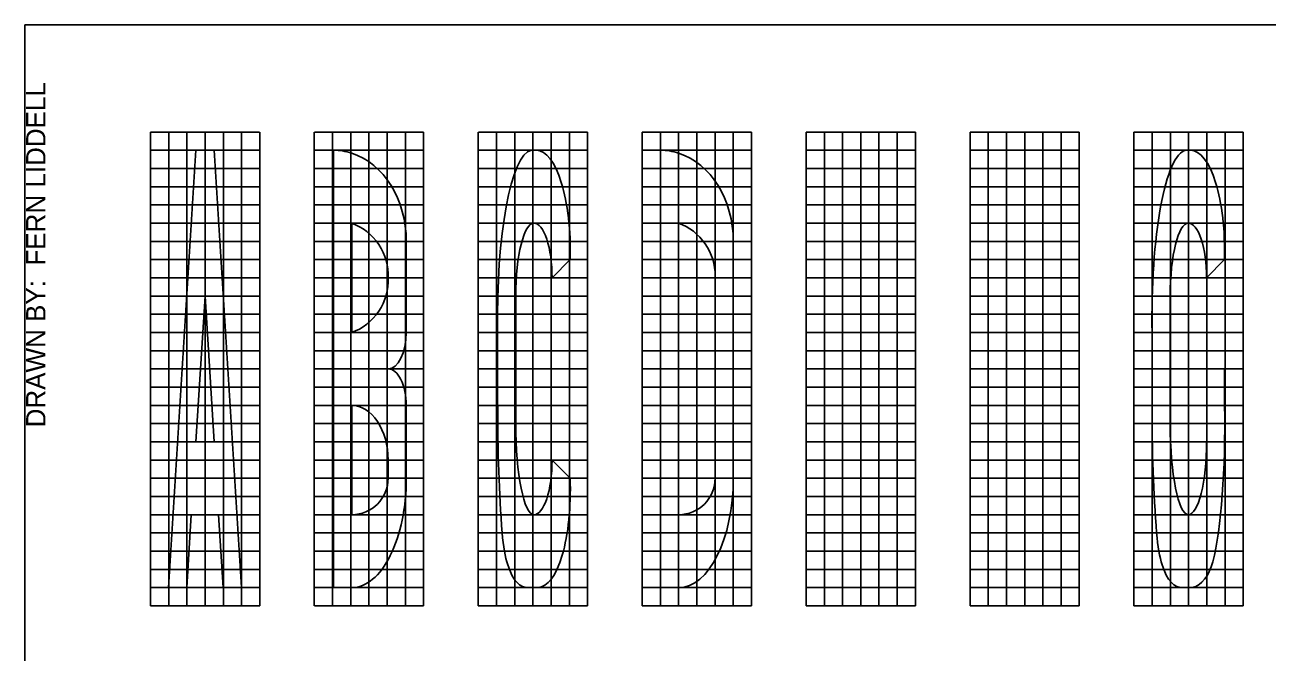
# Model space of a CAD drawing. Extents: x 99862 to 103151, y 100000 to 102076.
# Drawn here: x 99862 to 100885, y 101559 to 102076 of the extents above; entities that cross this region are included whole.
import ezdxf

# ---------------------------------------------------------------- set-up
doc = ezdxf.new("R2010")
doc.units = 0
for name, color, linetype in [('Level 1', 7, 'Continuous'), ('Level 20', 7, 'Continuous'), ('Level 4', 7, 'Continuous'), ('Level 62', 7, 'Continuous')]:
    doc.layers.add(name, color=color, linetype=linetype)

msp = doc.modelspace()

# ---------------------------------------------------------------- linework, layer by layer
at = {"layer": 'Level 1'}
msp.add_lwpolyline([(99862, 99999.5), (103151, 99999.5), (103151, 102075.5), (99862, 102075.5)], close=True, dxfattribs=at)
at = {"layer": 'Level 20'}
for p, q in [((100116.2, 101972.3), (100116.2, 101612.3)), ((100283.2, 101972.3), (100279.2, 101972.3)), ((100385.5, 101972.3), (100385.5, 101868.7)), ((100822.1, 101972.3), (100818.2, 101972.3)), ((100131.2, 101822.3), (100131.2, 101912.3)), ((100400.5, 101868.7), (100400.5, 101912.3)), ((100176.2, 101822.3), (100176.2, 101897.3)), ((100445.5, 101868.7), (100445.5, 101897.3)), ((100296.2, 101867.3), (100311.2, 101882.3)), ((100835.2, 101867.3), (100850.1, 101882.3)), ((100385.5, 101868.7), (100385.5, 101867.3)), ((100385.5, 101867.3), (100385.5, 101717.3)), ((100400.5, 101867.3), (100400.5, 101868.7)), ((100400.5, 101717.3), (100400.5, 101867.3)), ((100430.5, 101868.7), (100430.5, 101867.3)), ((100430.5, 101867.3), (100430.5, 101717.3)), ((100445.5, 101867.3), (100445.5, 101868.7)), ((100445.5, 101717.3), (100445.5, 101867.3)), ((100266.4, 101747.3), (100266.4, 101852.3)), ((100805.3, 101747.3), (100805.3, 101852.3)), ((100251.4, 101822.3), (100251.4, 101762.3)), ((100790.4, 101822.3), (100790.4, 101762.3)), ((100850.2, 101792.3), (100820.3, 101792.3)), ((100820.3, 101792.3), (100820.3, 101732.3)), ((100850.2, 101762.3), (100850.2, 101792.3)), ((100131.2, 101672.3), (100131.2, 101762.3)), ((100176.2, 101702.3), (100176.2, 101762.3)), ((100820.3, 101732.3), (100835.2, 101732.3)), ((100161.2, 101717.3), (100161.2, 101702.3)), ((100311.2, 101702.3), (100296.2, 101717.3)), ((100385.5, 101717.3), (100385.5, 101715.4)), ((100400.5, 101715.4), (100400.5, 101717.3)), ((100430.5, 101717.3), (100430.5, 101715.4)), ((100445.5, 101715.4), (100445.5, 101717.3)), ((100385.5, 101715.4), (100385.5, 101612.3)), ((100400.5, 101672.3), (100400.5, 101715.4)), ((100430.5, 101715.4), (100430.5, 101702.3)), ((100445.5, 101702.3), (100445.5, 101715.4)), ((100116.2, 101612.3), (100128.4, 101612.3)), ((100128.4, 101612.3), (100131.2, 101612.3)), ((100277.3, 101612.3), (100284.7, 101612.3)), ((100385.5, 101612.3), (100400.5, 101612.3)), ((100816.2, 101612.3), (100820.3, 101612.3)), ((100820.3, 101612.3), (100823.6, 101612.3))]:
    msp.add_line(p, q, dxfattribs=at)
for points in [[(99999.1, 101672.3), (100021.6, 101672.3), (100025.4, 101612.3), (100040.4, 101612.3), (100017.9, 101972.3), (100002.9, 101972.3), (99980.4, 101612.3), (99995.4, 101612.3)], [(100535.5, 101762.3), (100580.5, 101762.3), (100580.5, 101822.3), (100535.5, 101822.3), (100535.5, 101912.3), (100580.5, 101912.3), (100580.5, 101972.3), (100535.5, 101972.3), (100528, 101972.3), (100520.5, 101972.3), (100520.5, 101612.3), (100531.7, 101612.3), (100535.5, 101612.3), (100580.5, 101612.3), (100580.5, 101672.3), (100535.5, 101672.3)], [(100670.5, 101912.3), (100715.5, 101912.3), (100715.5, 101972.3), (100670.5, 101972.3), (100663, 101972.3), (100655.5, 101972.3), (100655.5, 101612.3), (100670.5, 101612.3), (100670.5, 101762.3), (100700.5, 101762.3), (100700.5, 101822.3), (100670.5, 101822.3)], [(100017.9, 101732.3), (100002.9, 101732.3), (100010.4, 101852.3)]]:
    msp.add_lwpolyline(points, close=True, dxfattribs=at)
for centre in [(100131.2, 101702.3), (100400.5, 101702.3)]:
    msp.add_arc(centre, 30, 270, 0, dxfattribs=at)
for centre, major_axis, ratio, start_param, end_param in [((100116.2, 101897.3), (0, -75), 0.8, 2.888912, 3.141593), ((100116.2, 101897.3), (0, -75), 0.8, 1.570796, 2.888912), ((100281.8, 101828.3), (1.4, -144.1), 0.211336, 3.181491, 4.752287), ((100281.3, 101882.8), (-2, -89.5), 0.334281, 1.57277, 3.143567), ((100385.5, 101897.3), (0, -75), 0.8, 2.888912, 3.141593), ((100385.5, 101897.3), (0, -75), 0.8, 1.570796, 2.888912), ((100820.8, 101828.3), (1.4, -144.1), 0.211348, 3.18149, 4.752287), ((100820.2, 101882.8), (-2, -89.5), 0.3343, 1.572771, 3.143568), ((100128.5, 101878), (21.2, -31.8), 0.784465, 0.785398, 2.356194), ((100281.3, 101852.3), (0, -60), 0.248912, 3.141593, 4.712389), ((100281.3, 101867.3), (0, -45), 0.331883, 1.570796, 3.141593), ((100397.8, 101878), (21.2, -31.8), 0.784465, 0.826187, 2.356194), ((100820.3, 101852.3), (0, -60), 0.248926, 3.141593, 4.712389), ((100820.3, 101867.3), (0, -45), 0.331902, 1.570796, 3.141593), ((100128.5, 101856.5), (-21.2, -31.8), 0.784465, 0.785398, 2.356194), ((100161.2, 101822.3), (0, -30), 0.5, 0, 1.570796), ((100161.2, 101762.3), (0, -30), 0.5, 1.570796, 3.141593), ((100131.2, 101717.3), (0, -45), 0.666667, 1.570796, 3.141593), ((100330.2, 101833.5), (-17.5, -354.3), 0.216739, 4.925571, 5.243712), ((100869.2, 101833.5), (-17.5, -354.3), 0.216751, 4.925572, 5.243713), ((100825.9, 101760), (2.2, -149), 0.16287, 0.554923, 1.58392), ((100281.3, 101747.3), (0, -75), 0.19913, 4.712389, 6.283185), ((100820.3, 101747.3), (0, -75), 0.199141, 4.712389, 6.283185), ((100820.3, 101732.3), (0, -60), 0.249371, 6.283185, 7.853982), ((100281.3, 101717.3), (0, -45), 0.331883, 6.283185, 7.853982), ((100131.2, 101702.3), (0, -90), 0.5, 6.283185, 7.853982), ((100281.6, 101701.5), (3.1, -89.2), 0.331181, 6.280966, 7.851763), ((100400.5, 101702.3), (0, -90), 0.5, 0, 1.570796), ((100272.7, 101702.4), (-5.6, -80.6), 0.216756, 5.320454, 5.812319), ((100811.7, 101702.4), (-5.6, -80.6), 0.216768, 5.320456, 5.812321), ((100312.6, 101794.8), (-38.4, -182.3), 0.244216, 5.877043, 6.350091), ((100851.5, 101794.8), (-38.4, -182.3), 0.244228, 5.877049, 6.350097), ((100586.8, 102189.6), (238.9, -576.6), 0.169025, 6.262693, 6.489624)]:
    msp.add_ellipse(centre, major_axis=major_axis, ratio=ratio, start_param=start_param, end_param=end_param, dxfattribs=at)
at = {"layer": 'Level 4'}
for p, q in [((99965.5, 101987.3), (99965.5, 101597.3)), ((99965.5, 101987.3), (100055.4, 101987.3)), ((99980.5, 101987.2), (99980.5, 101597.3)), ((99995.5, 101987.3), (99995.5, 101597.3)), ((100010.5, 101987.3), (100010.5, 101597.3)), ((100025.5, 101987.3), (100025.5, 101597.3)), ((100040.5, 101987.3), (100040.5, 101597.3)), ((100055.5, 101987.3), (100055.5, 101597.3)), ((100100.4, 101987.3), (100100.4, 101597.3)), ((100100.5, 101987.3), (100190.4, 101987.3)), ((100115.4, 101987.3), (100115.4, 101597.3)), ((100130.4, 101987.3), (100130.4, 101597.3)), ((100145.4, 101987.3), (100145.4, 101597.3)), ((100160.4, 101987.3), (100160.4, 101597.3)), ((100175.4, 101987.3), (100175.4, 101597.3)), ((100190.4, 101987.3), (100190.4, 101597.3)), ((100235.5, 101987.3), (100235.5, 101597.3)), ((100235.6, 101987.3), (100325.5, 101987.3)), ((100250.5, 101987.3), (100250.5, 101597.3)), ((100265.5, 101987.3), (100265.5, 101597.3)), ((100280.5, 101987.3), (100280.5, 101597.3)), ((100295.5, 101987.3), (100295.5, 101597.3)), ((100310.5, 101987.3), (100310.5, 101597.3)), ((100325.5, 101987.3), (100325.5, 101597.3)), ((100370.5, 101987.3), (100460.5, 101987.3)), ((100370.5, 101987.3), (100370.5, 101597.3)), ((100385.5, 101987.3), (100385.5, 101597.3)), ((100400.5, 101987.3), (100400.5, 101597.3)), ((100415.5, 101987.3), (100415.5, 101597.3)), ((100430.5, 101987.3), (100430.5, 101597.3)), ((100445.5, 101987.3), (100445.5, 101597.3)), ((100460.5, 101987.3), (100460.5, 101597.3)), ((100505.5, 101987.3), (100595.5, 101987.3)), ((100505.5, 101987.3), (100505.5, 101597.3)), ((100520.5, 101987.3), (100520.5, 101597.3)), ((100535.5, 101987.3), (100535.5, 101597.3)), ((100550.5, 101987.3), (100550.5, 101597.3)), ((100565.5, 101987.3), (100565.5, 101597.3)), ((100580.5, 101987.3), (100580.5, 101597.3)), ((100595.5, 101987.3), (100595.5, 101597.3)), ((100640.5, 101987.3), (100730.5, 101987.3)), ((100640.5, 101987.3), (100640.5, 101597.3)), ((100655.5, 101987.3), (100655.5, 101597.3)), ((100670.5, 101987.3), (100670.5, 101597.3)), ((100685.5, 101987.3), (100685.5, 101597.3)), ((100700.5, 101987.3), (100700.5, 101597.3)), ((100715.5, 101987.3), (100715.5, 101597.3)), ((100730.5, 101987.3), (100730.5, 101597.3)), ((100775.5, 101987.3), (100865.5, 101987.3)), ((100775.5, 101987.3), (100775.5, 101597.3)), ((100790.5, 101987.3), (100790.5, 101597.3)), ((100805.5, 101987.3), (100805.5, 101597.3)), ((100820.5, 101987.3), (100820.5, 101597.3)), ((100835.5, 101987.3), (100835.5, 101597.3)), ((100850.5, 101987.3), (100850.5, 101597.3)), ((100865.5, 101987.3), (100865.5, 101597.3)), ((99965.4, 101972.3), (100055.5, 101972.3)), ((100100.4, 101972.3), (100190.4, 101972.3)), ((100235.4, 101972.3), (100325.5, 101972.3)), ((100370.4, 101972.3), (100460.5, 101972.3)), ((100505.4, 101972.3), (100595.5, 101972.3)), ((100640.4, 101972.3), (100730.5, 101972.3)), ((100775.4, 101972.3), (100865.5, 101972.3)), ((99965.4, 101957.3), (100055.5, 101957.3)), ((100100.4, 101957.3), (100190.4, 101957.3)), ((100235.4, 101957.3), (100325.5, 101957.3)), ((100370.4, 101957.3), (100460.5, 101957.3)), ((100505.4, 101957.3), (100595.5, 101957.3)), ((100640.4, 101957.3), (100730.5, 101957.3)), ((100775.4, 101957.3), (100865.5, 101957.3)), ((99965.6, 101942.3), (100055.5, 101942.3)), ((100100.6, 101942.3), (100190.4, 101942.3)), ((100235.6, 101942.3), (100325.5, 101942.3)), ((100370.6, 101942.3), (100460.5, 101942.3)), ((100505.6, 101942.3), (100595.5, 101942.3)), ((100640.6, 101942.3), (100730.5, 101942.3)), ((100775.6, 101942.3), (100865.5, 101942.3)), ((99965.4, 101927.3), (100055.5, 101927.3)), ((100100.4, 101927.3), (100190.4, 101927.3)), ((100235.4, 101927.3), (100325.5, 101927.3)), ((100370.4, 101927.3), (100460.5, 101927.3)), ((100505.4, 101927.3), (100595.5, 101927.3)), ((100640.4, 101927.3), (100730.5, 101927.3)), ((100775.4, 101927.3), (100865.5, 101927.3)), ((99965.4, 101912.3), (100055.5, 101912.3)), ((100100.4, 101912.3), (100190.4, 101912.3)), ((100235.4, 101912.3), (100325.5, 101912.3)), ((100370.4, 101912.3), (100460.5, 101912.3)), ((100505.4, 101912.3), (100595.5, 101912.3)), ((100640.4, 101912.3), (100730.5, 101912.3)), ((100775.4, 101912.3), (100865.5, 101912.3)), ((99965.5, 101897.3), (100055.5, 101897.3)), ((100100.5, 101897.3), (100190.4, 101897.3)), ((100235.5, 101897.3), (100325.5, 101897.3)), ((100370.5, 101897.3), (100460.5, 101897.3)), ((100505.5, 101897.3), (100595.5, 101897.3)), ((100640.5, 101897.3), (100730.5, 101897.3)), ((100775.5, 101897.3), (100865.5, 101897.3)), ((99965.5, 101882.3), (100055.5, 101882.3)), ((100100.5, 101882.3), (100190.4, 101882.3)), ((100235.5, 101882.3), (100325.5, 101882.3)), ((100370.5, 101882.3), (100460.5, 101882.3)), ((100505.5, 101882.3), (100595.5, 101882.3)), ((100640.5, 101882.3), (100730.5, 101882.3)), ((100775.5, 101882.3), (100865.5, 101882.3)), ((99965.6, 101867.3), (100055.5, 101867.3)), ((100100.6, 101867.3), (100190.4, 101867.3)), ((100235.6, 101867.3), (100325.5, 101867.3)), ((100370.6, 101867.3), (100460.5, 101867.3)), ((100505.6, 101867.3), (100595.5, 101867.3)), ((100640.6, 101867.3), (100730.5, 101867.3)), ((100775.6, 101867.3), (100865.5, 101867.3)), ((99965.6, 101852.3), (100055.5, 101852.3)), ((100100.6, 101852.3), (100190.4, 101852.3)), ((100235.6, 101852.3), (100325.5, 101852.3)), ((100370.6, 101852.3), (100460.5, 101852.3)), ((100505.6, 101852.3), (100595.5, 101852.3)), ((100640.6, 101852.3), (100730.5, 101852.3)), ((100775.6, 101852.3), (100865.5, 101852.3)), ((99965.4, 101837.3), (100055.5, 101837.3)), ((100100.4, 101837.3), (100190.4, 101837.3)), ((100235.4, 101837.3), (100325.5, 101837.3)), ((100370.4, 101837.3), (100460.5, 101837.3)), ((100505.4, 101837.3), (100595.5, 101837.3)), ((100640.4, 101837.3), (100730.5, 101837.3)), ((100775.4, 101837.3), (100865.5, 101837.3)), ((99965.5, 101822.3), (100055.5, 101822.3)), ((100100.5, 101822.3), (100190.4, 101822.3)), ((100235.5, 101822.3), (100325.5, 101822.3)), ((100370.5, 101822.3), (100460.5, 101822.3)), ((100505.5, 101822.3), (100595.5, 101822.3)), ((100640.5, 101822.3), (100730.5, 101822.3)), ((100775.5, 101822.3), (100865.5, 101822.3)), ((99965.4, 101807.3), (100055.5, 101807.3)), ((100100.4, 101807.3), (100190.4, 101807.3)), ((100235.4, 101807.3), (100325.5, 101807.3)), ((100370.4, 101807.3), (100460.5, 101807.3)), ((100505.4, 101807.3), (100595.5, 101807.3)), ((100640.4, 101807.3), (100730.5, 101807.3)), ((100775.4, 101807.3), (100865.5, 101807.3)), ((99965.5, 101792.3), (100055.5, 101792.3)), ((100100.5, 101792.3), (100190.4, 101792.3)), ((100235.5, 101792.3), (100325.5, 101792.3)), ((100370.5, 101792.3), (100460.5, 101792.3)), ((100505.5, 101792.3), (100595.5, 101792.3)), ((100640.5, 101792.3), (100730.5, 101792.3)), ((100775.5, 101792.3), (100865.5, 101792.3)), ((99965.5, 101777.3), (100055.5, 101777.3)), ((100100.5, 101777.3), (100190.4, 101777.3)), ((100235.5, 101777.3), (100325.5, 101777.3)), ((100370.5, 101777.3), (100460.5, 101777.3)), ((100505.5, 101777.3), (100595.5, 101777.3)), ((100640.5, 101777.3), (100730.5, 101777.3)), ((100775.5, 101777.3), (100865.5, 101777.3)), ((99965.4, 101762.3), (100055.5, 101762.3)), ((100100.4, 101762.3), (100190.4, 101762.3)), ((100235.4, 101762.3), (100325.5, 101762.3)), ((100370.4, 101762.3), (100460.5, 101762.3)), ((100505.4, 101762.3), (100595.5, 101762.3)), ((100640.4, 101762.3), (100730.5, 101762.3)), ((100775.4, 101762.3), (100865.5, 101762.3)), ((99965.5, 101747.3), (100055.5, 101747.3)), ((100100.5, 101747.3), (100190.4, 101747.3)), ((100235.5, 101747.3), (100325.5, 101747.3)), ((100370.5, 101747.3), (100460.5, 101747.3)), ((100505.5, 101747.3), (100595.5, 101747.3)), ((100640.5, 101747.3), (100730.5, 101747.3)), ((100775.5, 101747.3), (100865.5, 101747.3)), ((99965.5, 101732.3), (100055.5, 101732.3)), ((100100.5, 101732.3), (100190.4, 101732.3)), ((100235.5, 101732.3), (100325.5, 101732.3)), ((100370.5, 101732.3), (100460.5, 101732.3)), ((100505.5, 101732.3), (100595.5, 101732.3)), ((100640.5, 101732.3), (100730.5, 101732.3)), ((100775.5, 101732.3), (100865.5, 101732.3)), ((99965.5, 101717.3), (100055.5, 101717.3)), ((100100.5, 101717.3), (100190.4, 101717.3)), ((100235.5, 101717.3), (100325.5, 101717.3)), ((100370.5, 101717.3), (100460.5, 101717.3)), ((100505.5, 101717.3), (100595.5, 101717.3)), ((100640.5, 101717.3), (100730.5, 101717.3)), ((100775.5, 101717.3), (100865.5, 101717.3)), ((99965.5, 101702.3), (100055.5, 101702.3)), ((100100.5, 101702.3), (100190.4, 101702.3)), ((100235.5, 101702.3), (100325.5, 101702.3)), ((100370.5, 101702.3), (100460.5, 101702.3)), ((100505.5, 101702.3), (100595.5, 101702.3)), ((100640.5, 101702.3), (100730.5, 101702.3)), ((100775.5, 101702.3), (100865.5, 101702.3)), ((99965.5, 101687.3), (100055.5, 101687.3)), ((100100.5, 101687.3), (100190.4, 101687.3)), ((100235.5, 101687.3), (100325.5, 101687.3)), ((100370.5, 101687.3), (100460.5, 101687.3)), ((100505.5, 101687.3), (100595.5, 101687.3)), ((100640.5, 101687.3), (100730.5, 101687.3)), ((100775.5, 101687.3), (100865.5, 101687.3)), ((99965.6, 101672.3), (100055.5, 101672.3)), ((100100.6, 101672.3), (100190.4, 101672.3)), ((100235.6, 101672.3), (100325.5, 101672.3)), ((100370.6, 101672.3), (100460.5, 101672.3)), ((100505.6, 101672.3), (100595.5, 101672.3)), ((100640.6, 101672.3), (100730.5, 101672.3)), ((100775.6, 101672.3), (100865.5, 101672.3)), ((99965.5, 101657.3), (100055.5, 101657.3)), ((100100.5, 101657.3), (100190.4, 101657.3)), ((100235.5, 101657.3), (100325.5, 101657.3)), ((100370.5, 101657.3), (100460.5, 101657.3)), ((100505.5, 101657.3), (100595.5, 101657.3)), ((100640.5, 101657.3), (100730.5, 101657.3)), ((100775.5, 101657.3), (100865.5, 101657.3)), ((99965.5, 101642.3), (100055.5, 101642.3)), ((100100.5, 101642.3), (100190.4, 101642.3)), ((100235.5, 101642.3), (100325.5, 101642.3)), ((100370.5, 101642.3), (100460.5, 101642.3)), ((100505.5, 101642.3), (100595.5, 101642.3)), ((100640.5, 101642.3), (100730.5, 101642.3)), ((100775.5, 101642.3), (100865.5, 101642.3)), ((99965.5, 101627.3), (100055.5, 101627.3)), ((100100.5, 101627.3), (100190.4, 101627.3)), ((100235.5, 101627.3), (100325.5, 101627.3)), ((100370.5, 101627.3), (100460.5, 101627.3)), ((100505.5, 101627.3), (100595.5, 101627.3)), ((100640.5, 101627.3), (100730.5, 101627.3)), ((100775.5, 101627.3), (100865.5, 101627.3)), ((99965.4, 101612.3), (100055.5, 101612.3)), ((100100.4, 101612.3), (100190.4, 101612.3)), ((100235.4, 101612.3), (100325.5, 101612.3)), ((100370.4, 101612.3), (100460.5, 101612.3)), ((100505.4, 101612.3), (100595.5, 101612.3)), ((100640.4, 101612.3), (100730.5, 101612.3)), ((100775.4, 101612.3), (100865.5, 101612.3)), ((99965.5, 101597.3), (100055.5, 101597.3)), ((100100.5, 101597.3), (100190.4, 101597.3)), ((100235.5, 101597.3), (100325.5, 101597.3)), ((100370.5, 101597.3), (100460.5, 101597.3)), ((100505.5, 101597.3), (100595.5, 101597.3)), ((100640.5, 101597.3), (100730.5, 101597.3)), ((100775.5, 101597.3), (100865.5, 101597.3))]:
    msp.add_line(p, q, dxfattribs=at)

# ---------------------------------------------------------------- texts
at = {"layer": 'Level 62'}
msp.add_text('DRAWN BY:  FERN LIDDELL', height=16, rotation=90, dxfattribs=at).set_placement((99879, 101744.2))

doc.saveas('drawing.dxf')
